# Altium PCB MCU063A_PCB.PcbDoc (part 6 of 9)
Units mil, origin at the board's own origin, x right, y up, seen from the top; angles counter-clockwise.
Board outline 4165.01 x 2371.03 mil, 10 copper layers (Top Layer, Internal Plane 2, Signal Layer 3, Signal Layer 4, Internal Plane 5, Internal Plane 6, Signal Layer 7, Signal Layer 8, Internal Plane 9, Bottom), stack 59.9 mil thick; 436 components, 392 nets, 1750 pads, 1250 vias.
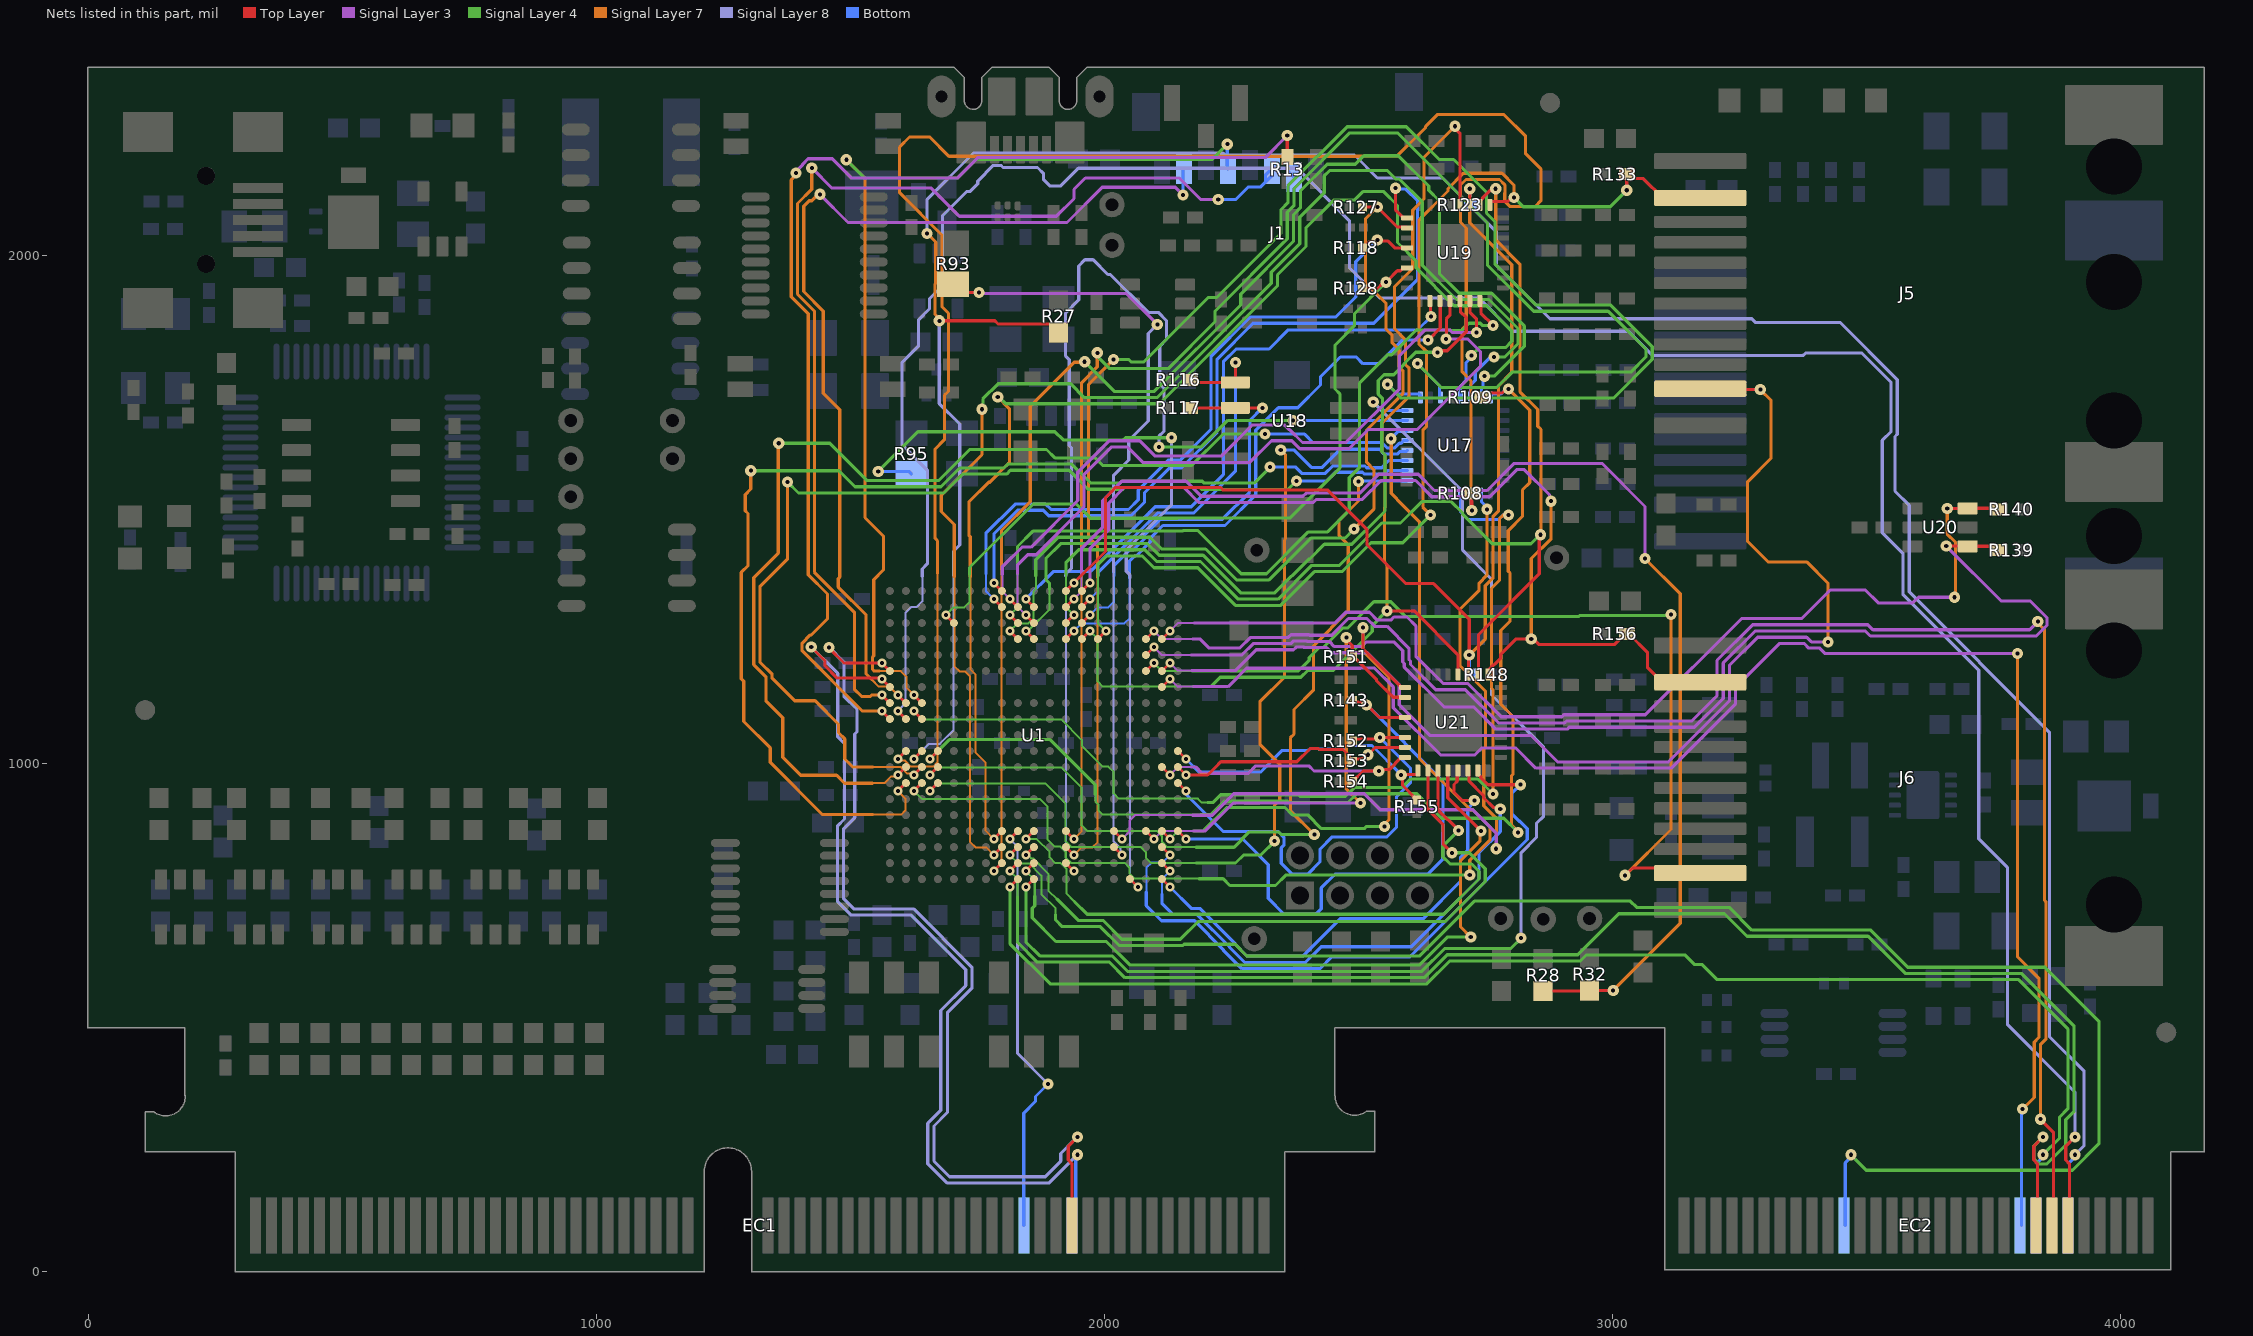
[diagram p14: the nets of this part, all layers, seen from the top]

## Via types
v1: diameter 22, hole 8, Top Layer to Bottom, tented both sides, 895 vias
v2: diameter 18, hole 8, Top Layer to Bottom, tented both sides, 334 vias
v3: diameter 19.68, hole 7.87, Top Layer to Bottom, 19 vias
v4: diameter 18/18/18/18/18/18 (per signal layer), hole 8, Top Layer to Bottom, tented both sides, 1 vias
v5: diameter 22/22/22/22/22/22 (per signal layer), hole 8, Top Layer to Bottom, tented both sides, 1 vias

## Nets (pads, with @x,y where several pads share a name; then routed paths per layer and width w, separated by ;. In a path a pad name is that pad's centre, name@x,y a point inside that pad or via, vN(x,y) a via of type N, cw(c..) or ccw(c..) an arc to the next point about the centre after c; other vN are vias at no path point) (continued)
MCU_GPIO98: EC1.95 U1.F1 | length 1909.8
  Top Layer w6.25: v1(1458.39,1228.64) 1458.39,1227.13 1487.69,1197.83 v2(1562.21,1197.83) U1.F1@1577.96,1182.08 ; EC1.95@1936.03,91 1936.03,212.49 1928.85,219.66 1928.85,246.88 v1(1946.98,265)
  Signal Layer 8 w6.25: v1(1458.39,1228.64) 1487.38,1199.65 1487.38,1132.34 1513.13,1106.59 1513.13,1062.49 1508.74,1058.09 1508.74,893.6 1486.83,871.7 1486.83,733.73 1506.75,713.81 1624.65,713.81 1739.38,599.08 1739.38,557.77 1691.06,509.44 1691.06,313.09 1664.63,286.67 1664.63,217.42 1695.24,186.81 1883.75,186.81 1914.36,217.42 1914.36,232.38 v1(1946.98,265)
MCU_GPIO99: EC1.96 U1.G1 | length 1924.5
  Top Layer w6.25: v1(1423.21,1229.31) 1450.27,1202.25 1450.27,1192.17 1474.31,1168.13 1560.42,1168.13 v2(1562.21,1166.34) U1.G1@1577.96,1150.59
  Signal Layer 8 w6.25: v1(1423.21,1229.31) 1475.13,1177.38 1475.13,1052.34 1488.58,1038.89 1488.58,890.77 1474.58,876.77 1474.58,728.66 1501.68,701.56 1619.58,701.56 1727.13,594 1727.13,562.84 1678.13,513.84 1678.13,317.49 1652.38,291.74 1652.38,212.34 1690.17,174.56 1891.54,174.56 v1(1946.98,230)
  Bottom w6.25: EC1.96@1936.03,91 1943.73,98.7 1943.73,222.49 1946.98,225.74 v1(1946.98,230)
MCU_GPIO100: J1.3 U1.H1 | length 2236.3
  Top Layer w6.25: v2(1562.21,1134.84) U1.H1@1577.96,1119.09
  Signal Layer 3 w6.25: v1(1424.21,2172.31) 1463.96,2132.56 1659.28,2132.56 1714.65,2077.19 1905.71,2077.19 1940.33,2111.8 1940.33,2130.07 1962.7,2152.44 2147.21,2152.44 2189.64,2110 v1(2224.21,2110)
  Signal Layer 7 w6.25: v1(1424.21,2172.31) 1424.21,2130.29 1396.07,2102.15 1396.07,1923.9 1429.38,1890.58 1429.38,1376.75 1508.13,1298 1508.13,1146.24 1522.5,1131.88 1539.28,1131.88 1542.25,1134.84 v2(1562.21,1134.84)
  Bottom w6.25: v1(2224.21,2110) 2258.9,2110 2283.71,2134.81 2307.71,2134.81 J1.3@2317.02,2144.13 ; J1.3@2317.02,2144.13 2317.02,2157.69 J1.3@2329.65,2170.31 2329.65,2156.75 J1.3@2317.02,2144.13
MCU_GPIO101: J1.7 U1.H2 | length 1942.3
  Top Layer w6.25: v2(1593.7,1134.84) U1.H2@1609.45,1119.09
  Signal Layer 3 w6.25: v1(1440.21,2120.31) 1495.58,2064.94 1926.46,2064.94 1995.65,2134.13 2139.88,2134.13 v1(2155.01,2119)
  Signal Layer 7 w4: 1542,1165.33 1555.99,1151.34 1577.21,1151.34 v2(1593.7,1134.84)
  Signal Layer 7 w6.25: v1(1440.21,2120.31) 1436.63,2120.31 1424.01,2107.69 1418.94,2107.69 1408.32,2097.07 1408.32,1928.97 1446.88,1890.41 1446.88,1728.88 1479.33,1696.43 1479.33,1366.8 1476.34,1363.81 1476.34,1347.12 1531.21,1292.25 1531.21,1176.12 1542,1165.33
  Bottom w6.25: v1(2155.01,2119) 2155.01,2168.9 J1.7@2156.42,2170.31
MCU_GPIO102: J1.5 U1.H3 | length 2020.7
  Top Layer w6.25: v2(1625.2,1134.84) U1.H3@1640.95,1119.09
  Signal Layer 4 w6.25: v1(1492.21,2188.31) 1528.33,2152.19 1710.45,2152.19 1747.64,2189.38 2212.38,2189.38 v1(2242.01,2219)
  Signal Layer 7 w4: 1556.99,1181.84 1599.42,1181.84 1610.2,1171.05 1610.2,1149.84 v2(1625.2,1134.84)
  Signal Layer 7 w6.25: v1(1492.21,2188.31) 1528.88,2151.63 1528.88,1484 1565.33,1447.55 1565.33,1381.24 1546.08,1361.99 1546.08,1212 1544,1209.92 1544,1185 1547.16,1181.84 1556.99,1181.84
  Bottom w6.25: v1(2242.01,2219) 2242.01,2171.34 J1.5@2243.03,2170.31
MCU_GPIO103: J1.2 R13.1 U1.J1 | length 2385.4
  Top Layer w6.25: v2(1562.21,1103.34) U1.J1@1577.96,1087.6 ; R13.1@2360.01,2193.62 v1(2360.01,2236)
  Signal Layer 3 w6.25: v1(1393.21,2162.31) 1393.21,2165.38 1406.08,2178.25 1406.08,2179.82 1416.7,2190.44 1464.45,2190.44 1502.7,2152.19 1710.45,2152.19 1750.85,2192.59 2316.6,2192.59 v1(2360.01,2236)
  Signal Layer 7 w6.25: v1(1393.21,2162.31) 1393.21,2158.05 1383.82,2148.66 1383.82,1918.82 1417.13,1885.51 1417.13,1371.68 1455.13,1333.68 1455.13,1284.61 1423.71,1253.19 1421.45,1253.19 1405.08,1236.82 1405.08,1221.8 1523.54,1103.34 v2(1562.21,1103.34)
  Bottom w6.25: v1(2360.01,2236) 2360.33,2235.68 2360.33,2167.19 J1.2@2372.96,2154.56
MCU_GPIO104: EC2.169 U1.J2 | length 5097.2
  Top Layer w6.25: v2(1593.7,1103.34) U1.J2@1609.45,1087.6 ; EC2.169@3899.34,91 3899.34,212.49 3892.16,219.67 3892.16,246.88 v1(3910.28,265)
  Signal Layer 8 w4: v2(1593.7,1103.34) 1608.7,1118.34 1608.7,1297.04 1619.73,1308.07 1630.66,1308.07 1641.7,1319.1 1641.7,1368
  Signal Layer 8 w6.25: 1641.7,1368 1641.7,1382.86 1651.83,1393 1651.83,1577.44 1601.88,1627.39 1601.88,1789.92 1634.38,1822.42 1634.38,1873.45 1655.83,1894.89 1655.83,1914.84 1681.58,1940.59 1681.58,2078.64 1728.63,2125.69 1735.21,2125.69 1750.76,2141.23 1750.76,2146.38 1781.5,2177.13 1796.52,2177.13 1800.52,2173.13 1868.52,2173.13 1880.51,2161.13 1880.51,2148.87 1892.5,2136.88 1914.14,2136.88 1948.89,2171.63 2379.34,2171.63 2482.38,2068.58 2482.38,1976.18 2542.13,1916.44 2736.71,1916.44 2802.34,1850.81 3030.83,1850.81 3078.46,1803.19 3375.71,1803.19 3380.46,1807.94 3490.86,1807.94 3548.33,1750.47 3548.33,1653.13 3531.08,1635.88 3531.08,1454.56 3571.58,1414.06 3571.58,1332.98 3721.05,1183.52 3721.05,851.84 3777.33,795.55 3777.33,486.55 3910.28,353.6 v1(3910.28,265)
MCU_GPIO105: U1.J3 U17.20 | length 2013
  Top Layer w6.25: v2(1625.2,1103.34) U1.J3@1640.95,1087.6
  Signal Layer 4 w4: v2(1625.2,1103.34) 1641.7,1086.85 1914.88,1086.85 1955.91,1045.82 1955.91,1034.89 1996.94,993.86 2007.87,993.86 2018.15,983.57 2018.15,941.15 2028.43,930.86 2184.14,930.86 2192,923 2203,923
  Signal Layer 4 w6.25: 2203,923 2213.57,923 2229.2,938.63 2382.22,938.63 2385.22,935.63 2474.56,935.63 2491.63,952.69 2585.21,952.69 2601.96,969.44 2735.64,969.44 v1(2764.99,940.09)
  Signal Layer 7 w6.25: v1(2764.99,940.09) 2764.99,1145.54 2762.08,1148.45 2762.08,1344.91 2777.46,1360.28 2777.46,1481.56 2784.89,1489 v1(2795.5,1489)
  Bottom w6.25: U17.20@2700.92,1531.57 2700.92,1494.97 2715.7,1480.19 2776.08,1480.19 2784.89,1489 v1(2795.5,1489)
MCU_GPIO106: R108.2 U1.L2 U17.19 | length 3755.2
  Top Layer w6.25: v2(1593.7,1008.86) U1.L2@1609.45,1024.6 ; v1(2723.21,1498.31) 2723.21,1530.24 R108.2@2724.54,1531.57
  Signal Layer 7 w4: v2(1593.7,1008.86) 1596.38,1006.18 1606.66,1006.18 1618.99,993.86 1662.91,993.86 1671.7,1002.64 1671.7,1373.8
  Signal Layer 7 w6.25: 1671.7,1373.8 1671.7,1438.14 1666.83,1443 1666.83,1619.01 1685.13,1637.32 1685.13,1724.56 1693.33,1732.76 1693.33,1885.86 1680.38,1898.81 1680.38,2039.77 1597.08,2123.07 1597.08,2213.71 1616.5,2233.13 1656.21,2233.13 1694.15,2195.19 2509.71,2195.19 2510.85,2196.32 2576.85,2196.32 2632.33,2251.8 2632.33,2254.07 2655.39,2277.13 2786.52,2277.13 2829.13,2234.51 2829.13,2200.24 2859.13,2170.24 2859.13,2107.49 2847.83,2096.19 2798.7,2096.19 2788.08,2106.8 2788.08,2122.69 2788.33,2122.94 2788.33,2138.82 2777.71,2149.44 2711.7,2149.44 2701.08,2138.82 2701.08,2065.17 2712.33,2053.92 2712.33,1862.8 2704.08,1854.55 2704.08,1771.07 2721.35,1753.8 2721.35,1500.17 v1(2723.21,1498.31)
  Bottom w6.25: U17.19@2720.6,1531.57 2721.9,1530.27 2721.9,1499.62 v1(2723.21,1498.31)
MCU_GPIO107: EC2.170 R27.2 U1.L3 | length 5456.3
  Top Layer w6.25: v2(1625.2,1008.86) U1.L3@1640.95,1024.6 ; v1(1675.21,1871.31) 1784.4,1871.31 1790.64,1865.06 1894.43,1865.06 1910.01,1849.49 R27.2@1910.01,1848.5
  Signal Layer 7 w6.25: v1(1651.21,2043.31) 1668.13,2026.38 1668.13,1945.49 1666.71,1944.07 1666.71,1884.07 1675.21,1875.57 v1(1675.21,1871.31)
  Signal Layer 8 w4: v2(1625.2,1008.86) 1654.93,1038.58 1676.14,1038.58 1703.19,1065.63 1703.19,1369
  Signal Layer 8 w6.25: v1(1651.21,2043.31) 1651.21,2110.27 1742.56,2201.63 2233.75,2201.63 2237.75,2197.63 2492.26,2197.63 2537.45,2152.44 2665.71,2152.44 2771.39,2046.76 2771.39,1980.99 2877.07,1875.31 3274.07,1875.31 3281.11,1868.26 3447.86,1868.26 3560.58,1755.54 3560.58,1648.06 3556.08,1643.56 3556.08,1536.07 3584.08,1508.07 3584.08,1337.8 3860.08,1061.8 3860.08,462.8 3928.41,394.48 3928.41,248.13 v1(3910.28,230) ; v1(1675.21,1871.31) 1675.21,1708.44 1715.33,1668.31 1715.33,1430 1703.19,1417.86 1703.19,1369
  Bottom w6.25: EC2.170@3899.34,91 3899.34,214.05 3915.28,230 v1(3910.28,230)
MCU_GPIO108: R109.1 U1.L4 U17.8 | length 2369.8
  Top Layer w6.25: v2(1656.7,1008.86) U1.L4@1672.44,1024.6 ; R109.1@2744.22,1720.55 2752.91,1729.24 2782.87,1729.24 2790.95,1737.31 v1(2795.21,1737.31)
  Signal Layer 4 w4: 1982.21,939.31 1982.21,925.03 1988.15,919.08 1988.15,908.15 1996.94,899.37 2189.78,899.37
  Signal Layer 4 w6.25: v2(1656.7,1008.86) 1694.97,1047.13 1893.2,1047.13 1982.21,958.12 1982.21,939.31 ; 2189.78,899.37 2209.61,899.37 2235.93,925.69 2360.56,925.69 2362.87,923.38 2479.64,923.38 2496.7,940.44 2615.26,940.44 2663.51,892.19 2786.33,892.19 v1(2814.21,864.31)
  Signal Layer 7 w6.25: v1(2795.21,1737.31) 2837.33,1695.19 2837.33,1552.8 2823.08,1538.55 2823.08,1486.32 2795.08,1458.32 2795.08,1378.44 2798.33,1375.19 2798.33,1280.07 2780.08,1261.82 2780.08,1116.8 2804.33,1092.55 2804.33,978.8 2801.08,975.55 2801.08,880 2814.21,866.88 v1(2814.21,864.31)
  Bottom w6.25: U17.8@2759.97,1720.55 2759.97,1725.47 2761.77,1727.27 2780.9,1727.27 2790.95,1737.31 v1(2795.21,1737.31)
MCU_GPIO109: U1.N2 U17.27 | length 2359.2
  Top Layer w6.25: v2(1593.7,945.86) U1.N2@1609.45,961.61
  Signal Layer 4 w6.25: v1(1304.21,1576.31) 1477.67,1576.31 1509.36,1544.63 1678.56,1544.63 1715.81,1581.88 1802.52,1581.88 1810.02,1589.38 1935.75,1589.38 1972.94,1552.19 2031.13,1552.19 2034.63,1555.69 2192.78,1555.69 2196.59,1551.88 2294.77,1551.88 v1(2326.21,1583.31)
  Signal Layer 7 w4: 1544.26,899.37 1599.92,899.37 1608.7,908.15 1608.7,930.86 v2(1593.7,945.86)
  Signal Layer 7 w6.25: v1(1304.21,1576.31) 1304.21,1540.34 1293.08,1529.21 1293.08,1497.5 1298.58,1492 1298.58,1389.34 1285.33,1376.09 1285.33,1166.82 1290.33,1161.82 1290.33,1082.82 1342.46,1030.69 1342.46,1002.27 1445.36,899.37 1544.26,899.37
  Bottom w6.25: v1@2330.21,1583.31 2376.84,1583.31 2389.53,1570.63 2434.14,1570.63 2449.21,1585.69 2513.09,1585.69 2516.59,1582.19 2545.97,1582.19 2560.32,1596.54 U17.27@2596.58,1596.54
MCU_GPIO110: U1.M2 U17.29 | length 2287.7
  Top Layer w6.25: v2(1593.7,977.36) U1.M2@1609.45,993.11
  Signal Layer 4 w6.25: v1(1359.21,1630.31) 1459.59,1630.31 1533.03,1556.88 1673.49,1556.88 1734.74,1618.13 1886.25,1618.13 1902.75,1601.63 1981.53,1601.63 1996.28,1586.88 2172.09,1586.88 2233.53,1648.31 v1(2316.21,1648.31)
  Signal Layer 7 w4: 1543.21,961.31 1567.37,961.31 1580.74,974.68 1591.02,974.68 v2(1593.7,977.36)
  Signal Layer 7 w6.25: v1(1359.21,1630.31) 1358.08,1629.19 1358.08,1414.19 1309.83,1365.94 1309.83,1194.73 1333.83,1170.73 1333.83,1123.36 1366.96,1090.24 1366.96,1012.42 1402.5,976.88 1473,976.88 1488.56,961.31 1543.21,961.31
  Bottom w6.25: v1(2316.21,1648.31) 2394.07,1648.31 2410.5,1631.88 2545.6,1631.88 2556.29,1621.19 2571.71,1621.19 2580.79,1630.27 2584.06,1630.27 2589.69,1635.91 U17.29@2596.58,1635.91
MCU_GPIO111: U1.M4 U17.25 | length 1797
  Top Layer w6.25: v2(1656.7,977.36) U1.M4@1672.44,993.11
  Signal Layer 4 w4: v2(1656.7,977.36) 1671.7,992.36 1914.88,992.36 1955.16,952.08 1955.16,878.15 1965.9,867.42 2102.81,867.42 2113.4,856.83 2113.4,845.9 2123.99,835.31 2180.21,835.31
  Signal Layer 4 w6.25: 2180.21,835.31 2255.31,835.31 2285.44,865.44 2342.71,865.44 2347.84,860.31 v1(2413.21,860.31)
  Signal Layer 7 w6.25: v1(2413.21,860.31) 2366.08,907.44 2366.08,1050.55 2373.33,1057.8 2373.33,1106.44 2411.88,1144.99 2411.88,1231.99 2480.21,1300.31 2480.21,1430.35 2461.53,1449.02 2461.53,1478 2500.21,1516.68 v1(2500.21,1555.31)
  Bottom w6.25: v1(2500.21,1555.31) 2501.13,1556.24 2595.66,1556.24 U17.25@2596.58,1557.17
MCU_GPIO112: U1.M3 U17.26 | length 2118.2
  Top Layer w6.25: v2(1625.2,977.36) U1.M3@1640.95,993.11
  Signal Layer 4 w6.25: v1(1376.21,1554.31) 1398.14,1532.38 1683.64,1532.38 1720.89,1569.63 1807.59,1569.63 1815.09,1577.13 1930.67,1577.13 1967.86,1539.94 2036.2,1539.94 2039.7,1543.44 2187.7,1543.44 2191.52,1539.63 2361.52,1539.63 v1(2378.21,1556.31)
  Signal Layer 7 w4: 1544.41,993.11 1599.17,993.11 1612.24,980.04 1622.52,980.04 v2(1625.2,977.36)
  Signal Layer 7 w6.25: v1(1376.21,1554.31) 1376.21,1401.99 1322.08,1347.86 1322.08,1199.8 1346.08,1175.8 1346.08,1167.8 1390.45,1123.44 1430.71,1123.44 1476.88,1077.27 1476.88,1060.63 1489,1048.52 1489,1009 1504.89,993.11 1544.41,993.11
  Bottom w6.25: v1(2378.21,1556.31) 2378.21,1557.31 2379.21,1556.31 2437.16,1556.31 2454.28,1573.44 2507.71,1573.44 2511.21,1569.94 2551.04,1569.94 2557.96,1576.85 U17.26@2596.58,1576.85
MCU_GPIO113: U1.N4 U17.28 | length 1940.1
  Top Layer w6.25: v2(1656.7,945.86) U1.N4@1672.44,961.61
  Signal Layer 4 w4: v2(1656.7,945.86) 1671.7,960.86 1883.38,960.86 1923.66,920.58 1923.66,846.66 1934.32,836 2071.24,836 2081.71,825.53 2081.71,814.6 2092.17,804.13 2181.03,804.13
  Signal Layer 4 w6.25: 2181.03,804.13 2258.13,804.13 2274,820 2307.89,820 v1(2335.21,847.31)
  Signal Layer 7 w6.25: v1(2335.21,847.31) 2335.21,918.68 2345.33,928.81 2345.33,998.75 2306.08,1038 2306.08,1121.44 2354.63,1169.99 2354.63,1439.7 2356.58,1441.64 2356.58,1607.94 v1(2347.21,1617.31)
  Bottom w6.25: v1(2347.21,1617.31) 2373.05,1617.31 2407.49,1582.88 2429.07,1582.88 2464.63,1618.44 2541.71,1618.44 2551.21,1608.94 2576.79,1608.94 2582.28,1614.42 2594.79,1614.42 U17.28@2596.58,1616.22
MCU_GPIO114: U1.N3 U17.30 | length 2250.4
  Top Layer w6.25: v2(1625.2,945.86) U1.N3@1640.95,961.61
  Signal Layer 4 w4: v2(1625.2,945.86) 1640.75,930.31 1873.21,930.31 1887.83,915.69 1887.83,851 1902.45,836.38 1913.38,836.38 1924.04,825.72 1924.04,814.79 1934.34,804.49 2039.76,804.49 2049.88,794.36 2049.88,783.43 2060,773.31 2186.21,773.31
  Signal Layer 4 w6.25: 2186.21,773.31 2233.69,773.31 2247,760 2336.87,760 2357.18,780.31 v1(2719.21,780.31)
  Signal Layer 7 w6.25: v1(2564.21,1639.31) 2564.58,1638.94 2564.58,1531.57 2587.65,1508.51 2620.08,1476.07 2620.08,1009.8 2720.7,909.19 2724.96,909.19 2759.33,874.82 2759.33,849.76 2719.21,809.63 v1(2719.21,780.31)
  Bottom w6.25: v1(2564.21,1639.31) 2578.69,1653.79 2594.79,1653.79 U17.30@2596.58,1655.59
MCU_GPIO115: U1.V12 U17.31 | length 2239.9
  Top Layer w6.25: U1.V12@1924.41,804.13 v2(1940.16,788.38)
  Signal Layer 4 w6.25: v1(2107.39,1623.13) 2191.02,1623.13 2243.21,1675.31 v1(2371.21,1675.31)
  Signal Layer 8 w4: 1924.21,1369 1924.21,804.34 v2(1940.16,788.38)
  Signal Layer 8 w6.25: 1924.21,1369 1924.21,1373.31 1935.33,1384.44 1935.33,1621.48 1930.91,1625.91 1930.91,1794.74 1923.82,1801.82 1923.82,1886.76 1949.58,1912.52 1949.58,1979.32 1961.7,1991.44 1977.99,1991.44 2006.99,1962.44 2011.71,1962.44 2086.28,1887.88 2106.28,1887.88 2122.33,1871.82 2122.33,1834.96 2108.88,1821.51 2108.88,1747.34 2117.33,1738.89 2117.33,1653.8 2107.39,1643.87 v1(2107.39,1623.13)
  Bottom w6.25: v1(2371.21,1675.31) U17.31@2596.58,1675.28
MCU_GPIO116: U1.W10 U17.32 | length 2442.4
  Top Layer w6.25: v2(1845.67,756.89) U1.W10@1861.42,772.63
  Signal Layer 4 w6.25: v2(1845.67,756.89) 1845.67,648.71 1873.07,621.31 2015.16,621.31 2045.54,590.94 2624.76,590.94 2669.76,635.94 2799.83,635.94 v1(2820.21,656.31)
  Signal Layer 8 w6.25: v1(2529.21,1711.31) 2705.08,1535.44 2705.08,1420.07 2762.08,1363.07 2762.08,1134.8 2864.58,1032.3 2864.58,896.32 2850.58,882.32 2850.58,854.62 2820.21,824.25 v1(2820.21,656.31)
  Bottom w6.25: v1(2529.21,1711.31) 2545.56,1694.96 U17.32@2596.58,1694.96
MCU_GPIO117: U1.U12 U17.1 | length 3277
  Top Layer w6.25: U1.U12@1924.41,835.63 v2(1940.16,819.88)
  Signal Layer 4 w6.25: v1(2018.21,1795.31) 2047.45,1795.31 2052.58,1790.19 2077.56,1790.19 2204.59,1917.21 2220.86,1917.21 2347.88,2044.24 2347.88,2090.36 2361.33,2103.8 2361.33,2136.93 2477.78,2253.38 2594.51,2253.38 2659.16,2188.72 2687.43,2188.72 2752.08,2124.07 2752.08,2083.39 2768.74,2066.74 2768.74,1983.64 2850.05,1902.33 2996.63,1902.33 3078.38,1820.58 3078.38,1795.42 3002.15,1719.19 2584.33,1719.19 v1(2557.21,1746.31)
  Signal Layer 7 w4: v2(1940.16,819.88) 1955.16,834.88 1976.37,834.88 1986.66,845.16 1986.66,1366
  Signal Layer 7 w6.25: 1986.66,1366 1986.66,1427.43 1969.08,1445 1969.08,1746.19 v1(2018.21,1795.31)
  Bottom w6.25: v1(2557.21,1746.31) 2576.25,1727.27 2620.38,1727.27 2622.17,1725.47 U17.1@2622.17,1720.55
MCU_GPIO118: U1.T12 U17.3 | length 3169.7
  Top Layer w6.25: U1.T12@1924.41,867.12 v2(1940.16,851.38)
  Signal Layer 4 w6.25: v1(1986.21,1808.31) 1989.22,1805.3 1989.22,1798.67 2010.7,1777.19 2125.83,1777.19 2217.75,1869.11 2217.75,1890.53 2360.13,2032.92 2360.13,2085.28 2373.58,2098.73 2373.58,2131.85 2482.85,2241.13 2577.03,2241.13 2754.22,2063.93 2754.22,1980.83 2844.97,1890.08 2991.56,1890.08 3066.13,1815.51 3066.13,1800.49 3035.98,1770.34 2802.6,1770.34 2772.45,1740.19 2663.33,1740.19 v1(2616.21,1787.31)
  Signal Layer 7 w4: v2(1940.16,851.38) 1955.16,866.38 1955.16,1369.26
  Signal Layer 7 w6.25: 1955.16,1369.26 1955.16,1749.59 1986.21,1780.64 v1(1986.21,1808.31)
  Bottom w6.25: v1(2616.21,1787.31) 2659.75,1743.77 2659.75,1722.35 U17.3@2661.54,1720.55
MCU_GPIO119: U1.T15 U17.18 | length 1630.1
  Top Layer w6.25: U1.T15@2018.9,867.12 v2(2034.65,851.38)
  Signal Layer 3 w4: v2(2034.65,851.38) 2049.65,866.38 2049.65,887.59 2060.37,898.31 2173.21,898.31
  Signal Layer 3 w6.25: 2173.21,898.31 2212.25,898.31 2254.38,940.44 2511.71,940.44 2542.96,909.19 2724.96,909.19 2771.21,862.94 v1(2771.21,832.31)
  Signal Layer 7 w6.25: v1(2753.21,1500.31) 2752.96,1500.06 2752.96,1370.43 2737.58,1355.05 2737.58,1341.05 2700.08,1303.55 2700.08,1192.72 2750.28,1142.52 2750.28,1031.68 2746.86,1028.26 2746.86,917.02 2771.58,892.3 2771.58,832.69 v1(2771.21,832.31)
  Bottom w6.25: U17.18@2740.29,1531.57 2742.08,1529.78 2742.08,1515.7 2753.21,1504.57 v1(2753.21,1500.31)
MCU_GPIO120: R93.1 U1.U15 | length 1543.7
  Top Layer w6.25: R93.1@1702.51,1943.66 1718.86,1927.31 v1(1753.21,1927.31) ; U1.U15@2018.9,835.63 v2(2034.65,819.88)
  Signal Layer 3 w6.25: v1(1753.21,1927.31) 1755.67,1924.85 2043.67,1924.85 v1(2104.21,1864.31)
  Signal Layer 8 w4: 2018.21,1377.31 2018.21,846.6 2031.97,832.84 2031.97,822.56 v2(2034.65,819.88)
  Signal Layer 8 w6.25: 2018.21,1377.31 2018.21,1567.57 2048.13,1597.49 2048.13,1635.87 2086.33,1674.07 2086.33,1846.44 v1(2104.21,1864.31)
MCU_GPIO121: R95.1 U1.W16 | length 1638.3
  Top Layer w6.25: U1.W16@2050.4,772.63 v2(2066.14,756.89)
  Signal Layer 4 w6.25: v1(1555.01,1575) 1633.13,1653.13 1902.52,1653.13 1918.77,1636.88 2037.52,1636.88 2041.95,1641.31 v1(2132.21,1641.31)
  Signal Layer 8 w4: 2050.21,1365.31 2050.21,772.82 v2(2066.14,756.89)
  Signal Layer 8 w6.25: 2050.21,1365.31 2050.21,1371.31 2043.21,1378.31 2043.21,1420.31 2132.21,1509.31 v1(2132.21,1641.31)
  Bottom w6.25: v1(1555.01,1575) 1615.01,1575 R95.1@1620.01,1570
MCU_GPIO122: U1.T8 U17.5 | length 2548
  Top Layer w6.25: v2(1782.68,851.38) U1.T8@1798.43,867.12
  Signal Layer 4 w6.25: v1(1790.21,1721.31) 1792.39,1721.31 1805.71,1708 2108.61,1708 2340.88,1940.27 2340.88,1961.69 2396.88,2017.69 2396.88,2054.51 2451.25,2108.88 2492.11,2108.88 2508.93,2125.69 2549.79,2125.69 2577.08,2098.39 2577.08,2025.39 2613.55,1988.93 2613.55,1975.57 2688.06,1901.06 2752.09,1901.06 2801.99,1851.16 2801.99,1831.03 2789.63,1818.68 2737.58,1818.68 v1(2722.21,1803.31)
  Signal Layer 7 w4: 1736.18,1366.93 1736.18,1185.19 1746,1175.38 1746,1021.97 1766.18,1001.78 1766.18,867.87 v2(1782.68,851.38)
  Signal Layer 7 w6.25: 1736.18,1366.93 1736.18,1446.25 1733.44,1449 1733.44,1514.82 1772.27,1553.66 1774.3,1553.66 1813.13,1592.49 1813.13,1698.38 v1(1790.21,1721.31)
  Bottom w6.25: U17.5@2700.92,1720.55 2700.92,1742.39 2711.55,1753.02 2711.55,1788.39 2722.21,1799.05 v1(2722.21,1803.31)
MCU_GPIO123: U1.U8 U17.6 | length 2733.1
  Top Layer w6.25: v2(1782.68,819.88) U1.U8@1798.43,835.63
  Signal Layer 4 w6.25: v1(1759.21,1697.31) 1760.95,1699.05 1760.95,1717.69 1790.82,1747.56 1933.52,1747.56 1960.84,1720.25 2103.54,1720.25 2328.63,1945.34 2328.63,1966.77 2384.63,2022.77 2384.63,2075.13 2432.88,2123.38 2432.88,2156.51 2443.5,2167.13 2556.65,2167.13 2573.34,2150.44 2580.71,2150.44 2625.8,2105.35 2625.8,1980.65 2693.13,1913.31 2757.16,1913.31 2814.24,1856.24 2814.24,1825.96 2788.59,1800.31 v1(2767.21,1800.31)
  Signal Layer 7 w4: 1704.69,1366.83 1704.69,1191.62 1714.88,1181.43 1725.81,1181.43 1736,1171.24 1736,845.35 1746.47,834.88 1767.68,834.88 v2(1782.68,819.88)
  Signal Layer 7 w6.25: 1704.69,1366.83 1704.69,1470.39 1679.08,1496 1679.08,1527.82 1759.21,1607.94 v1(1759.21,1697.31)
  Bottom w6.25: U17.6@2720.6,1720.55 2720.6,1744.75 2730.08,1754.23 2730.08,1769.82 2757.56,1797.3 2764.19,1797.3 v1(2767.21,1800.31)
MCU_GPIO124: U1.V8 U17.7 | length 2669.5
  Top Layer w6.25: v2(1782.68,788.38) U1.V8@1798.43,804.13
  Signal Layer 4 w6.25: v1(1961.28,1790.81) 2019.6,1732.5 2098.46,1732.5 2268.45,1902.48 2268.45,1923.9 2372.38,2027.84 2372.38,2080.21 2385.83,2093.66 2385.83,2126.78 2438.43,2179.38 2493.9,2179.38 2510.85,2196.32 2578.71,2196.32 2638.46,2136.58 2638.46,2128.43 2659.73,2107.15 2659.73,1964.04 2698.21,1925.56 2762.24,1925.56 2826.49,1861.31 2826.49,1820.89 2768.58,1762.98 2748.87,1762.98 v1(2748.21,1762.31)
  Signal Layer 7 w4: v2(1782.68,788.38) 1797.68,803.38 1797.68,1381.78
  Signal Layer 7 w6.25: 1797.68,1381.78 1797.68,1458.6 1854.08,1515 1854.08,1702.95 1940.91,1789.78 1960.25,1789.78 v1(1961.28,1790.81)
  Bottom w6.25: U17.7@2740.29,1720.55 2742.08,1722.35 2742.08,1739.42 2745.19,1742.54 2745.19,1759.3 v1(2748.21,1762.31)
MCU_GPIO125: EC1.90 U1.T9 | length 833.5
  Top Layer w6.25: v2(1814.18,851.38) U1.T9@1829.92,867.12
  Signal Layer 8 w4: v2(1814.18,851.38) 1829.21,836.34 1829.21,729.31
  Signal Layer 8 w6.25: 1829.21,729.31 1829.21,429.31 v1(1889.21,369.31)
  Bottom w6.25: EC1.90@1841.54,91 1841.54,312.01 1864.45,334.93 1864.45,344.56 v1(1889.21,369.31)
MCU_GPIO126: EC2.142 U1.U9 | length 3341.4
  Top Layer w6.25: v2(1814.18,819.88) U1.U9@1829.92,835.63
  Signal Layer 4 w4: v2(1814.18,819.88) 1830.67,803.38 1851.88,803.38 1876,779.27 1876,743 1904,715 1904,703
  Signal Layer 4 w6.25: 1904,703 1904,692 1917.07,678.93 1992.19,678.93 2029.19,641.94 2154.79,641.94 2157.29,644.44 2257.31,644.44 2280.87,620.88 2620.05,620.88 2728.3,729.13 3035.25,729.13 3047.5,716.88 3229.82,716.88 3274.51,672.19 3508.29,672.19 3581.29,599.19 3850.96,599.19 3957.33,492.82 3957.33,251.42 3905.54,199.63 3499.71,199.63 v1(3469.34,230)
  Bottom w6.25: EC2.142@3458.39,91 3458.39,214.05 3474.34,230 v1(3469.34,230)
MCU_GPIO127: EC2.165 U1.V9 | length 2978.5
  Top Layer w6.25: v2(1814.18,788.38) U1.V9@1829.92,804.13 ; EC2.165@3836.34,91 3836.34,212.49 3829.17,219.67 3829.17,246.88 v1(3847.29,265)
  Signal Layer 4 w4: v2(1814.18,788.38) 1829.18,773.38 1829.18,739.34
  Signal Layer 4 w6.25: 1829.18,739.34 1829.18,647.88 1867.99,609.06 2010.09,609.06 2040.46,578.69 2629.84,578.69 2674.84,623.69 2931.96,623.69 3012.47,704.2 3220.5,704.2 3264.76,659.94 3503.21,659.94 3576.21,586.94 3804.54,586.94 3908.58,482.89 3908.58,315.34 3892.16,298.92 3892.16,249.24 3854.8,211.88 3839.78,211.88 3829.17,222.49 3829.17,246.88 v1(3847.29,265)
MCU_GPIO128: EC2.166 U1.W9 | length 2751.4
  Top Layer w6.25: v2(1814.18,756.89) U1.W9@1829.92,772.63
  Signal Layer 4 w6.25: v2(1814.18,756.89) 1814.18,645.55 1893.54,566.19 2634.66,566.19 2679.91,611.44 2937.03,611.44 2949.03,623.44 3142.45,623.44 3161.7,604.19 3176.96,604.19 3206.46,574.69 3799.46,574.69 3896.33,477.82 3896.33,320.42 3879.91,303.99 3879.91,262.62 v1(3847.29,230)
  Bottom w6.25: EC2.166@3836.34,91 3836.34,214.05 3852.29,230 v1(3847.29,230)
MCU_GPIO129: U1.T10 U21.3 | length 1336.7
  Top Layer w6.25: v2(1845.67,851.38) U1.T10@1861.42,867.12 ; U21.3@2656.54,986.57 2656.54,908.97 v1(2697.21,868.31)
  Signal Layer 4 w4: v2(1845.67,851.38) 1866.88,851.38 1892.17,826.09 1892.17,815.16 1903.2,804.13 1914.13,804.13 1925.16,793.1 1925.16,744.36 1941.21,728.31
  Signal Layer 4 w6.25: 1941.21,728.31 1966.09,703.43 2667.96,703.43 2737.33,772.8 2737.33,787.82 2722.84,802.31 2680.57,802.31 2666.08,816.8 2666.08,837.19 v1(2697.21,868.31)
MCU_GPIO130: U1.U10 U21.2 | length 1346.6
  Top Layer w6.25: v2(1845.67,819.88) U1.U10@1861.42,835.63 ; U21.2@2636.86,986.57 2636.86,910.29 2666.33,880.82 2666.33,842.19 v1(2684.21,824.31)
  Signal Layer 4 w4: v2(1845.67,819.88) 1849.46,819.88 1855.96,813.38 1859.62,813.38 1890,783 1890,750 1907,733
  Signal Layer 4 w6.25: 1907,733 1948.82,691.18 1997.27,691.18 2034.26,654.19 2149.71,654.19 2184.65,689.13 2670.98,689.13 2749.58,767.73 2749.58,792.89 2718.16,824.31 v1(2684.21,824.31)
MCU_GPIO131: U1.V10 U21.4 | length 1428.5
  Top Layer w6.25: v2(1845.67,788.38) U1.V10@1861.42,804.13 ; U21.4@2676.23,986.57 2675.83,986.18 2675.83,932.69 v1(2741.21,867.31)
  Signal Layer 4 w4: v2(1845.67,788.38) 1863,771.05 1863,739
  Signal Layer 4 w6.25: 1863,739 1863,720 1858.21,715.21 1858.21,696.17 1904.7,649.68 2004.12,649.68 2050.61,603.19 2619.69,603.19 2674.81,658.31 v1(2721.21,658.31)
  Signal Layer 7 w6.25: v1(2721.21,658.31) 2701.08,678.44 2701.08,808.83 2739.19,846.94 2739.19,865.29 v1(2741.21,867.31)
MCU_GPIO132: U1.W18 U21.5 | length 975.6
  Top Layer w6.25: U1.W18@2113.39,772.63 v2(2129.14,756.89) ; U21.5@2695.92,986.57 2694.65,985.31 2694.65,965.39 2688.08,958.82 2688.08,943.8 2704.57,927.31 v1(2728.21,927.31)
  Bottom w6.25: v2(2129.14,756.89) 2171.09,714.94 2187.86,714.94 2258.83,643.97 2258.83,642.92 2280.87,620.88 2390.8,620.88 2464.41,694.48 2627.48,694.48 2701.08,768.09 2701.08,815.55 2715.33,829.8 2715.33,911.37 2728.21,924.25 v1(2728.21,927.31)
MCU_GPIO133: EC2.164 U1.G18 | length 3114.5
  Top Layer w6.25: U1.G18@2113.39,1150.59 v2(2129.14,1166.34)
  Signal Layer 3 w4: v2(2129.14,1166.34) 2144.16,1151.31 2175.21,1151.31
  Signal Layer 3 w6.25: 2175.21,1151.31 2243.53,1151.31 2279.71,1187.49 2504.42,1187.49 2504.92,1187.99 2531.57,1187.99 2568.76,1150.8 2568.76,1109.81 2661.72,1016.85 2728.88,1016.85 2742.6,1030.57 2809.76,1030.57 2849.39,990.94 3115.45,990.94 3242.46,1117.94 3242.46,1149.84 3329.05,1236.44 3377.13,1236.44 3386.51,1227.06 3408.09,1227.06 3418.84,1216.31 v1(3797.21,1216.31)
  Signal Layer 7 w6.25: v1(3797.21,1216.31) 3797.21,619.68 3839.33,577.55 3839.33,460.8 3830.04,451.51 3830.04,342.75 v1(3807.29,320)
  Bottom w6.25: EC2.164@3804.85,91 3804.85,317.56 v1(3807.29,320)
MCU_GPIO134: U1.V18 U21.6 | length 1096.7
  Top Layer w6.25: U1.V18@2113.39,804.13 v2(2129.14,788.38) ; U21.6@2715.6,986.57 2717.4,984.78 2717.4,965.76 2746.33,936.82 2746.33,933.12 2766.12,913.33 2776.19,913.33 v1(2779.21,910.31)
  Bottom w4: 2113.21,743.31 2113.21,772.45 v2(2129.14,788.38)
  Bottom w6.25: 2113.21,743.31 2113.21,724.79 2135.31,702.69 2182.79,702.69 2246.58,638.89 2246.58,637.84 2275.8,608.63 2395.87,608.63 2426.59,639.34 2603.87,639.34 2737.33,772.8 2737.33,824.07 2779.21,865.94 v1(2779.21,910.31)
MCU_GPIO135: U1.U18 U21.7 | length 1289.4
  Top Layer w6.25: U1.U18@2113.39,835.63 v2(2129.14,819.88) ; U21.7@2735.29,986.57 2735.29,979.69 2740.92,974.05 2740.92,972.14 2754.75,958.31 v1(2819.21,958.31)
  Bottom w4: 2082.64,747 2082.64,794.6 2092.92,804.88 2114.14,804.88 v2(2129.14,819.88)
  Bottom w6.25: 2082.64,747 2082.64,720.36 2112.56,690.44 2177.71,690.44 2234.33,633.82 2234.33,632.77 2270.73,596.38 2424.48,596.38 2447.79,619.69 2601.54,619.69 2832.33,850.48 2832.33,871.82 2817.84,886.31 2816.57,886.31 2802.08,900.8 2802.08,941.19 v1(2819.21,958.31)
MCU_GPIO136: R151.2 U1.T17 U21.26 | length 977
  Top Layer w6.25: U1.T17@2081.89,867.12 v2(2097.64,851.38) ; v1(2476.21,1248.31) 2476.21,1244.05 2488,1232.26 R151.2@2488,1210 2491.15,1210 2535.33,1165.82 2535.33,1163.46 2568.51,1130.28 U21.26@2591.58,1130.28
  Signal Layer 3 w4: v2(2097.64,851.38) 2113.58,867.31 2174.21,867.31
  Signal Layer 3 w6.25: 2174.21,867.31 2198.57,867.31 2253.57,922.31 v1(2504.21,922.31)
  Signal Layer 7 w6.25: v1(2476.21,1248.31) 2476.21,950.31 v1(2504.21,922.31)
MCU_GPIO137: U1.T18 U21.25 | length 1060.8
  Top Layer w6.25: U1.T18@2113.39,867.12 v2(2129.14,851.38) ; v1(2509.21,1267.31) 2509.21,1225.45 2584.69,1149.96 U21.25@2591.58,1149.96
  Signal Layer 4 w4: v2(2129.14,851.38) 2145.07,867.31 2176.21,867.31
  Signal Layer 4 w6.25: 2176.21,867.31 2194.88,867.31 2241.01,913.44 2355.48,913.44 2370.04,898.88 2400.28,898.88 2427.28,871.88 2511.52,871.88 2515.63,875.99 v1(2551.21,875.99)
  Signal Layer 7 w6.25: v1(2509.21,1267.31) 2509.21,1221.31 2560.33,1170.19 2560.33,889.37 2551.21,880.25 v1(2551.21,875.99)
MCU_GPIO138: R143.1 U1.T19 U21.28 | length 1180.4
  Top Layer w6.25: U1.T19@2144.88,867.12 v2(2160.63,851.38) ; R143.1@2488,1125 2492.18,1120.83 2506.43,1120.83 2511.95,1115.31 v1(2516.21,1115.31) 2540.61,1090.91 U21.28@2591.58,1090.91
  Bottom w6.25: v2(2160.63,851.38) 2272.1,851.38 2322.58,800.89 2322.58,734.52 2353.67,703.43 2416.35,703.43 2427.07,714.15 2427.07,755.31 2453.93,782.17 2636.42,782.17 2666.08,811.83 2666.08,865.55 2666.33,865.8 2666.33,965.19 v1(2516.21,1115.31)
MCU_GPIO139: R152.2 U1.N19 U21.30 | length 917.8
  Top Layer w6.25: U1.N19@2144.88,961.61 v2(2160.63,945.86) ; R152.2@2488,1045 2491.3,1048.3 2539.19,1048.3 2542.32,1051.42 2591.47,1051.42 U21.30@2591.58,1051.54
  Bottom w6.25: v2(2160.63,945.86) 2162.88,943.61 2162.88,937.01 2233.7,866.19 2341.96,866.19 2353.33,854.82 2353.33,839.06 2348.33,834.05 2348.33,803.66 2369.81,782.17 2400.2,782.17 2424.38,806.35 2424.38,831.37 2448.55,855.54 2556.39,855.54 2575.08,874.23 2575.08,934.87 2602.33,962.12 2602.33,991.19 v1(2542.21,1051.31)
MCU_GPIO140: R153.2 U1.M19 U21.31 | length 499
  Top Layer w6.25: U1.M19@2144.88,993.11 v2(2160.63,977.36) 2203.16,977.36 2218.75,992.95 2229.47,1003.67 2378.93,1003.67 2404.7,1029.44 2421.45,1029.44 2423.28,1027.61 2469.64,1027.61 2482.07,1015.17 2482.07,1010.14 2487.21,1005 R153.2@2488,1005 2491.8,1008.8 2506.43,1008.8 2514.95,1017.31 v1(2519.21,1017.31) 2533.75,1031.85 U21.31@2591.58,1031.85
MCU_GPIO141: R154.2 U1.M18 U21.32 | length 578.3
  Top Layer w6.25: U1.M18@2113.39,993.11 v2(2129.14,977.36) ; R154.2@2488,965 2488.79,965 2509.1,985.31 v1(2540.21,985.31) 2542.95,988.05 2560.58,988.05 2584.69,1012.17 U21.32@2591.58,1012.17
  Signal Layer 3 w4: v2(2129.14,977.36) 2145.09,993.31 2171.21,993.31
  Signal Layer 3 w6.25: 2171.21,993.31 2179.69,993.31 2192,981 2283.72,981 2298.15,995.44 2402.45,995.44 2412.57,985.31 v1(2540.21,985.31)
MCU_GPIO142: R155.2 U1.L19 U21.1 | length 606.2
  Top Layer w6.25: U1.L19@2144.88,1024.6 v2(2160.63,1008.86) ; R155.2@2615.01,927.99 2615.01,928.78 2586.85,956.94 2586.85,974.67 v1(2584.21,977.31) 2585.48,978.58 2615.38,978.58 2617.17,980.38 U21.1@2617.17,986.57
  Bottom w6.25: v2(2160.63,1008.86) 2186.44,983.05 2307.31,983.05 2350.14,1025.88 2401.14,1025.88 2404.7,1029.44 2421.45,1029.44 2422.7,1028.19 2471.08,1028.19 2478.33,1035.44 2526.71,1035.44 2584.21,977.94 v1(2584.21,977.31)
MCU_GPIO143: J5.11 U1.F18 | length 2361
  Top Layer w6.25: U1.F18@2113.39,1182.08 v2(2129.14,1197.83) ; J5.11@3170.84,1735.9 v1(3291.11,1735.9)
  Signal Layer 3 w4: v2(2129.14,1197.83) 2144.14,1182.83 2171.69,1182.83
  Signal Layer 3 w6.25: 2171.69,1182.83 2257.73,1182.83 2298.73,1223.83 2372.21,1223.83 2377.5,1229.13 2392.52,1229.13 2393.52,1228.13 2437.52,1228.13 2447.71,1217.94 2517.95,1217.94 2580.31,1155.58 2580.31,1115.59 2640.46,1055.44 2839.66,1055.44 2891.91,1003.19 3110.38,1003.19 3230.21,1123.02 3230.21,1192.94 3285.95,1248.69 3382.21,1248.69 3391.58,1239.31 v1(3424.21,1239.31)
  Signal Layer 7 w6.25: v1(3291.11,1735.9) 3312.13,1714.88 3312.13,1600.87 3266.08,1554.82 3266.08,1436.96 3306.16,1396.88 3382.28,1396.88 3424.21,1354.94 v1(3424.21,1239.31)
MCU_GPIO144: J6.11 U1.F17 | length 1848.1
  Top Layer w6.25: U1.F17@2081.89,1182.08 v2(2097.64,1197.83) ; v1(3025.01,780) v1(3025.01,780) 3039.45,794.38 3160.07,794.38 3150.02,784.32 J6.11@3172.83,784.32
  Signal Layer 4 w4: v2(2097.64,1197.83) 2113.39,1182.08 2172.44,1182.08
  Signal Layer 4 w6.25: 2172.44,1182.08 2381.73,1182.08 2403.13,1203.49 2403.13,1208.76 2422.5,1228.13 2430.32,1228.13 2468.63,1266.44 2478.6,1266.44 2530.6,1318.44 2563.71,1318.44 2592.46,1289.69 2933.95,1289.69 2935.7,1291.44 3113.33,1291.44 v1(3115.21,1293.31)
  Signal Layer 7 w6.25: v1(3025.01,780) 3115.21,870.2 v1(3115.21,1293.31)
MCU_GPIO145: R139.1 U1.E17 U20.1 | length 2407.9
  Top Layer w6.25: U1.E17@2081.89,1213.58 v2(2097.64,1229.33) ; v1(3657.01,1428) 3698.74,1428 U20.1@3699.14,1427.6 3753.79,1427.6 R139.1@3761.39,1420
  Signal Layer 3 w4: v2(2097.64,1229.33) 2113.39,1213.58 2170.94,1213.58
  Signal Layer 3 w6.25: 2170.94,1213.58 2270.37,1213.58 2292.87,1236.08 2367.13,1236.08 2372.43,1241.38 2397.59,1241.38 2398.59,1240.38 2442.59,1240.38 2452.78,1230.19 2506.62,1230.19 2515.87,1239.44 2569.71,1239.44 2587.21,1221.94 2587.21,1199.94 2590.33,1196.82 2590.33,1189.79 2668.78,1111.34 2727.04,1111.34 2770.69,1067.69 2910.95,1067.69 2914.7,1071.44 3161.3,1071.44 3217.96,1128.09 3217.96,1198.02 3280.88,1260.94 3497.63,1260.94 3507.63,1250.94 3834.46,1250.94 3855.33,1271.8 3855.33,1286.82 3822.28,1319.88 3765.13,1319.88 v1(3657.01,1428)
MCU_GPIO146: R140.1 U1.D18 U20.3 | length 2111
  Top Layer w6.25: U1.D18@2113.39,1245.08 v2(2129.14,1260.82) ; v1(3659.01,1502) 3698.74,1502 U20.3@3699.14,1502.4 3758.99,1502.4 R140.1@3761.39,1500
  Signal Layer 3 w4: v2(2129.14,1260.82) 2144.62,1276.31 2176.21,1276.31
  Signal Layer 3 w6.25: 2176.21,1276.31 2453.86,1276.31 2475.23,1297.69 2521.79,1297.69 2537.29,1282.19 2563.71,1282.19 2569.96,1288.44 2595.71,1288.44 2613.16,1271 2613.16,1211.08 2666.71,1157.52 2715.5,1157.52 2780.84,1092.19 2900.8,1092.19 2904.55,1095.94 3064.73,1095.94 3254.23,1285.44 3372.96,1285.44 3428.96,1341.44 3497.56,1341.44 3522.81,1316.19 3591.4,1316.19 3602.4,1327.19 3673.08,1327.19 v1(3673.21,1327.31)
  Signal Layer 7 w6.25: v1(3659.01,1502) 3659.01,1451.63 3675.13,1435.51 3675.13,1329.24 v1(3673.21,1327.31)
MCU_GPIO147: EC2.167 U1.D17 | length 3244.3
  Top Layer w6.25: U1.D17@2081.89,1245.08 v2(2097.64,1260.82) ; v1(3842.29,300) 3867.84,274.45 EC2.167@3867.84,91
  Signal Layer 3 w4: v2(2097.64,1260.82) 2113.15,1245.31 2173.21,1245.31
  Signal Layer 3 w6.25: 2173.21,1245.31 2187.69,1245.31 2205.38,1227.62 2267.08,1227.62 2287.79,1248.33 2362.06,1248.33 2367.35,1253.63 2402.67,1253.63 2403.67,1252.63 2447.49,1252.63 2480.3,1285.44 2516.71,1285.44 2532.21,1269.94 2556.54,1269.94 2599.46,1227.02 2599.46,1205.02 2602.58,1201.89 2602.58,1194.87 2652.17,1145.27 2710.42,1145.27 2775.76,1079.94 2905.88,1079.94 2909.63,1083.69 3156.23,1083.69 3205.71,1133.16 3205.71,1203.09 3275.8,1273.19 3502.7,1273.19 3512.7,1263.19 3821.08,1263.19 v1(3837.21,1279.31)
  Signal Layer 7 w6.25: v1(3837.21,1279.31) 3837.21,1276.85 3850.38,1263.67 3850.38,731.04 3853.13,728.29 3853.13,457.28 3842.29,446.44 v1(3842.29,300)
MCU_GPIO148: J5.2 R133.1 U1.D14 U19.17 | length 2287.7
  Top Layer w6.25: U1.D14@1987.4,1245.08 v2(2003.15,1260.82) ; U19.17@2758.91,2099.49 2758.91,2104.41 2760.7,2106.21 2793.84,2106.21 2801.95,2114.31 v1(2806.21,2114.31) ; v1(3028.21,2128.31) 3028.21,2159.58 R133.1@3028.63,2160 3037.32,2151.31 3060.89,2151.31 3099,2113.2 J5.2@3172.83,2113.2
  Signal Layer 4 w4: 1987.4,1369.12 1987.4,1276.57 v2(2003.15,1260.82)
  Signal Layer 4 w6.25: 1987.4,1369.12 1987.4,1391.4 2004.44,1408.44 2074.71,1408.44 2097.84,1385.31 2183.86,1385.31 2257.86,1311.31 2347.04,1311.31 2413.35,1377.63 2467.8,1377.63 2524.86,1434.69 2587.58,1434.69 v1(2642.21,1489.31) ; v1(2806.21,2114.31) 2824.64,2095.88 2995.77,2095.88 v1(3028.21,2128.31)
  Signal Layer 7 w6.25: v1(2642.21,1489.31) 2626.86,1504.66 2626.86,1656 2634.33,1663.47 2634.33,1810.55 2619.08,1825.8 2619.08,2069.55 2676.33,2126.8 2676.33,2131.39 2706.63,2161.69 2782.79,2161.69 2806.21,2138.27 v1(2806.21,2114.31)
MCU_GPIO149: J6.2 R156.1 U1.A13 U21.17 | length 1987.5
  Top Layer w6.25: U1.A13@1955.91,1339.56 v2(1971.66,1355.31) ; U21.17@2754.97,1175.55 2754.97,1182.44 2780.08,1207.55 2780.08,1214.82 2810.57,1245.31 2844.47,1245.31 2855.72,1234.06 3003.76,1234.06 3024.69,1255 3032.57,1255 3069.33,1218.24 3069.33,1188.37 3097.79,1159.91 J6.2@3172.83,1159.91
  Signal Layer 3 w6.25: v2(1971.66,1355.31) 1971.66,1422.91 2008.83,1460.09 2008.83,1512.57 2039.7,1543.44 2155.95,1543.44 2185.7,1513.69 2411.3,1513.69 2417.55,1519.94 2507.79,1519.94 2544.86,1557.01 2612.73,1557.01 2644.63,1525.1 2758.36,1525.1 2811.7,1578.44 2826.71,1578.44 2876.19,1528.96 2876.19,1519.33 v1(2879.21,1516.31)
  Signal Layer 7 w6.25: v1(2840.21,1245.31) 2840.33,1245.44 2840.33,1403.58 2879.21,1442.46 v1(2879.21,1516.31)
MCU_GPIO150: R116.1 U1.B13 U18.5 | length 777.9
  Top Layer w6.25: U1.B13@1955.91,1308.07 v2(1971.66,1323.82) ; R116.1@2168.63,1755 2173.63,1750 U18.5@2257.73,1750 2258.01,1750.28 v1(2258.01,1789)
  Bottom w4: v2(1971.66,1323.82) 1987.21,1339.37 1987.21,1369.31
  Bottom w6.25: 1987.21,1369.31 1987.21,1375.11 2105.16,1493.06 2176.03,1493.06 2258.01,1575.04 v1(2258.01,1789)
MCU_GPIO151: R117.1 U1.C13 U18.6 | length 801.1
  Top Layer w6.25: U1.C13@1955.91,1276.57 v2(1971.66,1292.32) ; R117.1@2168.63,1700 v1(2311.01,1700)
  Bottom w4: v2(1971.66,1292.32) 1986.66,1307.32 2007.87,1307.32 2018.9,1318.35 2018.9,1369
  Bottom w6.25: 2018.9,1369 2018.9,1389.48 2050.11,1420.69 2057.43,1420.69 2078.96,1442.21 2078.96,1449.53 2110.23,1480.81 2232.36,1480.81 2285.83,1534.29 2285.83,1660.89 2286.71,1661.77 2286.71,1675.7 v1(2311.01,1700)
MCU_GPIO152: U1.D13 U19.20 U21.20 | length 2185.7
  Top Layer w6.25: U1.D13@1955.91,1245.08 v2(1971.66,1260.82) ; v1(2556.21,1300.31) 2609.84,1300.31 2695.92,1214.24 U21.20@2695.92,1175.55 ; v1(2690.21,2254.31) 2690.21,2250.05 2699.85,2240.41 U19.20@2699.85,2099.49
  Signal Layer 4 w4: v2(1971.66,1260.82) 1986.66,1245.82 1986.66,1161.62 1996.96,1151.31 2173,1151.31
  Signal Layer 4 w6.25: 2173,1151.31 2209.31,1151.31 2227.83,1169.83 2386.8,1169.83 2400.09,1183.13 2450.65,1183.13 2527.33,1259.8 2527.33,1271.44 v1(2556.21,1300.31)
  Signal Layer 7 w6.25: v1(2556.21,1300.31) 2556.21,1391.68 2551.08,1396.8 2551.08,1501.69 2552.33,1502.94 2552.33,1607.82 2546.08,1614.07 2546.08,1669.19 2599.83,1722.94 2599.83,1778.05 2592.58,1785.3 2592.58,1833.89 2571.08,1855.39 2571.08,1938.55 2606.83,1974.3 2606.83,2089.3 2629.14,2111.61 2629.14,2193.24 v1(2690.21,2254.31)
MCU_GPIO153: R123.2 R148.2 U1.A12 U19.19 U21.19 | length 2270.3
  Top Layer w6.25: U1.A12@1924.41,1339.56 v2(1940.16,1355.31) 2002.21,1417.36 2002.21,1523.27 2022.38,1543.44 2228.54,1543.44 2233.79,1538.19 2439.96,1538.19 2516.83,1461.32 2516.83,1431.05 2593.7,1354.19 2647.96,1354.19 2718.21,1283.94 v1(2718.21,1213.31) 2716.9,1212.01 2716.9,1176.85 U21.19@2715.6,1175.55 ; v1(2719.21,2131.31) 2719.37,2131.15 2719.37,2099.65 U19.19@2719.54,2099.49
  Signal Layer 7 w6.25: v1(2718.21,1213.31) 2749.83,1244.94 2749.83,1349.98 2765.21,1365.36 2765.21,1486.68 2776.08,1497.55 2776.08,1743.82 2801.99,1769.73 2801.99,1981.58 2719.21,2064.37 v1(2719.21,2131.31)
  Bottom w6.25: v1(2718.21,1213.31) 2718.21,1183.69 2726.89,1175 R148.2@2727.77,1175 ; v1(2719.21,2131.31) 2719.21,2103.76 R123.2@2723.47,2099.49
MCU_GPIO154: R28.1 R32.1 U1.B12 | length 2595.7
  Top Layer w6.25: U1.B12@1924.41,1308.07 v2(1940.16,1323.82) ; R28.1@2863.71,552.2 R32.1@2953.71,552.2 ; R32.1@2955.01,553.5 v1(3001.51,553.5)
  Signal Layer 3 w4: v2(1940.16,1323.82) 1955.21,1338.86 1955.21,1371.31
  Signal Layer 3 w6.25: 1955.21,1371.31 1955.21,1423.79 1996.58,1465.17 1996.58,1517.64 2034.63,1555.69 2161.02,1555.69 2190.77,1525.94 2390.79,1525.94 2397.04,1532.19 2502.71,1532.19 2539.78,1569.26 2617.8,1569.26 2649.71,1537.35 2753.29,1537.35 2806.63,1590.69 2979.46,1590.69 3064.21,1505.94 v1(3064.21,1403.31)
  Signal Layer 7 w6.25: v1(3001.51,553.5) 3133.33,685.33 3133.33,1334.19 v1(3064.21,1403.31)
MCU_GPIO155: U1.C12 U19.18 U21.18 | length 2332.3
  Top Layer w6.25: U1.C12@1924.41,1276.57 v2(1940.16,1292.32) ; U21.18@2735.29,1175.55 2736.33,1176.6 2736.33,1253.83 2855.88,1373.38 2855.88,1447.99 v1(2858.21,1450.31) ; U19.18@2739.22,2099.49 2739.22,2106.38 2744.86,2112.02 2744.86,2113.93 2759.23,2128.3 2767.19,2128.3 v1(2770.21,2131.31)
  Signal Layer 4 w4: 1924.41,1372.11 1924.41,1308.07 v2(1940.16,1292.32)
  Signal Layer 4 w6.25: 1924.41,1372.11 1924.41,1395.41 1949.69,1420.69 2079.79,1420.69 2102.91,1397.56 2189.31,1397.56 2263.31,1323.56 2341.97,1323.56 2408.28,1389.88 2462.73,1389.88 2546.29,1473.44 2582.96,1473.44 2624.96,1515.44 2682.71,1515.44 2705.08,1493.07 2705.08,1490.8 2763.41,1432.47 2839.81,1432.47 2857.64,1450.31 v1(2858.21,1450.31)
  Signal Layer 7 w6.25: v1(2770.21,2131.31) 2770.21,2030.69 2817.88,1983.01 2817.88,1731.96 2853.08,1696.76 2853.08,1663.8 2859.33,1657.55 2859.33,1451.44 v1(2858.21,1450.31)
MCU_GPIO156: U1.D12 U19.3 | length 1208.6
  Top Layer w6.25: U1.D12@1924.41,1245.08 v2(1940.16,1260.82) ; v1(2637.21,1833.31) 2661.06,1857.16 2661.06,1909.94 U19.3@2660.48,1910.51
  Bottom w4: v2(1940.16,1260.82) 1955.16,1275.82 2039.36,1275.82 2049.65,1286.11 2049.65,1365
  Bottom w6.25: 2049.65,1365 2049.65,1382.24 2049.08,1382.8 2049.08,1397.82 2059.7,1408.44 2062.5,1408.44 2091.21,1437.14 2091.21,1444.46 2115.31,1468.56 2237.43,1468.56 2298.08,1529.21 2298.08,1655.82 2342.65,1700.39 2380.9,1700.39 2425.47,1744.97 2425.47,1761.1 2464.5,1800.13 2496.01,1800.13 2508.94,1787.19 2540.45,1787.19 2586.57,1833.31 v1(2637.21,1833.31)
MCU_GPIO157: U1.B10 U19.2 | length 1211.9
  Top Layer w6.25: v2(1845.67,1323.82) U1.B10@1861.42,1308.07 ; U19.2@2640.8,1910.51 2641.86,1909.45 2641.86,1880.77 v1(2642.93,1879.7)
  Bottom w6.25: v2(1845.67,1323.82) 1900.11,1378.25 1973.03,1378.25 2100.09,1505.31 2170.95,1505.31 2234.21,1568.57 2234.21,1790.83 2259.25,1815.88 2324.25,1815.88 2361.81,1853.44 2555.71,1853.44 2555.96,1853.19 2616.42,1853.19 v1(2642.93,1879.7)
MCU_GPIO158: U1.C10 U19.4 | length 1462.2
  Top Layer w6.25: v2(1845.67,1292.32) U1.C10@1861.42,1276.57 ; v1(2672.21,1835.31) 2673.31,1836.41 2673.31,1875.04 2680.17,1881.9 U19.4@2680.17,1910.51
  Signal Layer 3 w4: 1829.21,1374.31 1829.21,1308.78 v2(1845.67,1292.32)
  Signal Layer 3 w6.25: 1829.21,1374.31 1829.21,1391.21 1849,1411 1865.89,1411 1959.83,1504.94 1959.83,1568.57 2014.39,1623.13 2045.16,1623.13 2075.53,1592.75 2286.28,1592.75 2328.96,1635.44 2369.08,1635.44 2384.89,1619.63 2481.52,1619.63 2519.34,1657.44 2615.96,1657.44 2740.33,1781.8 2740.33,1810.82 2715.84,1835.31 v1(2672.21,1835.31)
MCU_GPIO159: U1.D10 U19.5 | length 1520.3
  Top Layer w6.25: v2(1845.67,1260.82) U1.D10@1861.42,1245.08 ; v1(2655.78,1809.31) 2658.79,1812.33 2674.85,1812.33 2712.33,1849.8 2712.33,1877.82 2700.83,1889.33 2700.83,1909.54 U19.5@2699.85,1910.51
  Signal Layer 4 w4: v2(1845.67,1260.82) 1849.46,1260.82 1854.46,1265.82 1854.53,1265.82 1892.17,1303.46 1892.17,1342.35
  Signal Layer 4 w6.25: 1892.17,1342.35 1892.17,1354.83 1885.26,1361.74 1885.26,1403.89 1914.31,1432.94 2084.86,1432.94 2107.99,1409.81 2194.38,1409.81 2268.38,1335.81 2335.68,1335.81 2401.99,1402.13 2403.68,1402.13 2433,1431.44 2486.96,1431.44 2552.33,1496.8 2552.33,1607.82 2546.08,1614.07 2546.08,1672.99 2547.33,1674.24 2547.33,1718.82 2539.08,1727.07 2539.08,1753.82 2550.45,1765.19 2569.71,1765.19 2589.64,1785.11 2589.64,1786.38 2612.57,1809.31 v1(2655.78,1809.31) v1@2656.78,1810.31
MCU_GPIO160: U1.B9 U19.6 | length 1412.4
  Top Layer w6.25: v2(1814.18,1323.82) U1.B9@1829.92,1308.07 ; U19.6@2719.54,1910.51 2719.54,1887.94 2732.21,1875.27 v1(2732.21,1848.31)
  Signal Layer 3 w4: 1799.18,1372.28 1799.18,1338.82 v2(1814.18,1323.82)
  Signal Layer 3 w6.25: 1799.18,1372.28 1799.18,1387.18 1838,1426 1855.85,1426 1947.58,1517.73 1947.58,1573.64 2009.31,1635.38 2069.51,1635.38 2099.89,1605 2230.12,1605 2291.56,1666.44 2354.45,1666.44 2363.7,1657.19 2364.66,1657.19 2389.97,1631.88 2475.4,1631.88 2580.33,1736.8 2580.33,1802.07 2631.7,1853.44 2679.71,1853.44 2684.84,1848.31 v1(2732.21,1848.31)
MCU_GPIO161: U1.C9 U19.7 | length 1548.2
  Top Layer w6.25: v2(1814.18,1292.32) U1.C9@1829.92,1276.57 ; U19.7@2739.22,1910.51 2741.02,1908.72 2741.02,1886.5 v1(2765.21,1862.31)
  Signal Layer 4 w4: v2(1814.18,1292.32) 1829.18,1307.32 1829.18,1371.28
  Signal Layer 4 w6.25: 1829.18,1371.28 1829.18,1427.18 1859.44,1457.44 2153.7,1457.44 2154.7,1458.44 2184.4,1458.44 2269.22,1373.63 2319.22,1373.63 2401.53,1455.94 2439.46,1455.94 2482.08,1498.55 2482.08,1562.82 2502.38,1583.12 2502.38,1749.12 2557.7,1804.44 2565.29,1804.44 2614.29,1853.44 2679.71,1853.44 2680.96,1852.19 2703.21,1852.19 2717.46,1866.44 2739.71,1866.44 2743.84,1862.31 v1(2765.21,1862.31)
MCU_GPIO162: R127.2 U1.D9 U19.26 | length 1747.1
  Top Layer w6.25: v2(1814.18,1260.82) U1.D9@1829.92,1245.08 ; R127.2@2508,2095 2508.16,2095.16 2537.05,2095.16 v1(2537.21,2095.31) 2576.51,2056.01 2593.73,2056.01 U19.26@2595.52,2054.21
  Signal Layer 4 w4: v2(1814.18,1260.82) 1829.18,1275.82 1850.39,1275.82 1860.67,1286.11 1860.67,1338.82 1865.17,1343.31 1865.17,1368.83
  Signal Layer 4 w6.25: 1865.17,1368.83 1865.17,1401.12 1909.24,1445.19 2089.94,1445.19 2112.94,1422.19 2199.33,1422.19 2260.14,1361.38 2324.29,1361.38 2406.6,1443.69 2473.58,1443.69 v1(2491.21,1461.31)
  Signal Layer 7 w6.25: v1(2491.21,1461.31) 2530.58,1500.69 2530.58,1578.3 2516.08,1592.8 2516.08,1656.51 2587.58,1728.01 2587.58,1772.98 2580.33,1780.23 2580.33,1814.17 2566.33,1828.17 2566.33,1842.82 2554.33,1854.82 2554.33,1905.82 2514.08,1946.07 2514.08,2072.19 v1(2537.21,2095.31)
MCU_GPIO163: U1.A8 U19.25 | length 1543.9
  Top Layer w6.25: v2(1782.68,1355.31) U1.A8@1798.43,1339.56 ; v1(2573.21,2132.31) 2573.21,2089.32 2588.63,2073.9 U19.25@2595.52,2073.9
  Bottom w6.25: v2(1782.68,1355.31) 1782.68,1451.76 1829.36,1498.44 1879.71,1498.44 1890.46,1487.69 2052.54,1487.69 2079.08,1514.23 2079.08,1532.82 2128.55,1582.29 2151.89,1582.29 2221.96,1652.36 2221.96,1795.9 2292.68,1866.63 2530.15,1866.63 2616.46,1952.93 2616.46,2107.69 2593.58,2130.57 2574.95,2130.57 v1(2573.21,2132.31)
MCU_GPIO164: R118.1 U1.B8 U19.28 | length 1412.6
  Top Layer w6.25: v2(1782.68,1323.82) U1.B8@1798.43,1308.07 ; R118.1@2508,2015 2508.79,2015 2521.09,2027.3 2534.19,2027.3 v1(2537.21,2030.31) 2538.91,2028.61 2557.58,2028.61 2571.35,2014.84 U19.28@2595.52,2014.84
  Bottom w4: 1766.93,1373.59 1766.93,1339.56 v2(1782.68,1323.82)
  Bottom w6.25: 1766.93,1373.59 1766.93,1453.33 1824.29,1510.69 1884.79,1510.69 1895.54,1499.94 2047.46,1499.94 2066.83,1519.3 2066.83,1537.89 2125.85,1596.91 2149.19,1596.91 2209.71,1657.44 2209.71,1800.98 2287.6,1878.88 2455.52,1878.88 2494.86,1918.21 2494.86,1987.96 v1(2537.21,2030.31)
MCU_GPIO165: R128.2 U1.C5 U19.30 | length 1506.7
  Top Layer w6.25: v2(1688.19,1292.32) U1.C5@1703.94,1276.57 ; R128.2@2508,1935 2537.7,1935 2547.21,1944.5 2547.21,1950.31 2557.21,1950.31 2576.73,1969.83 2582.99,1969.83 2588.63,1975.47 U19.30@2595.52,1975.47 ; v1@2547.21,1947.31 v1(2554.21,1947.31)
  Signal Layer 4 w4: v2(1688.19,1292.32) 1703.19,1307.32 1724.4,1307.32 1734.69,1317.6 1734.69,1371.83
  Signal Layer 4 w6.25: 1734.69,1371.83 1734.69,1385.75 1859.63,1510.69 1945.14,1510.69 1973.14,1482.69 2144.3,1482.69 2144.55,1482.94 2365.11,1482.94 2463.63,1581.46 2463.63,1727.45 2453.88,1737.2 2453.88,1823.49 2492.63,1862.24 2492.63,1885.74 v1(2554.21,1947.31)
